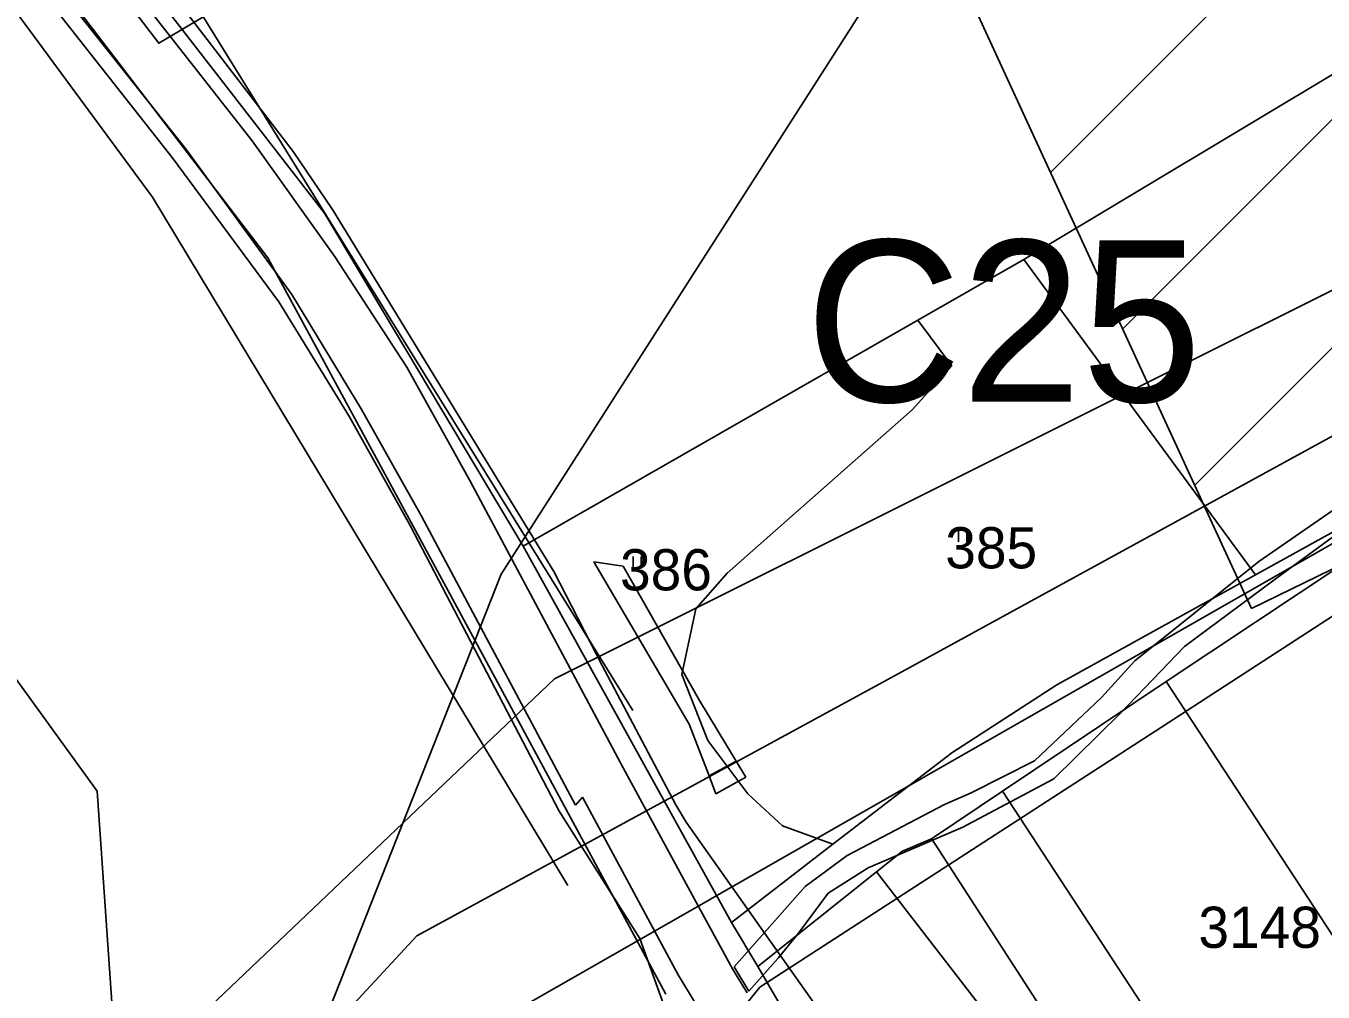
# Model space of a CAD drawing. Extents: x -564810 to -550519, y -1045831 to -1034011.
# Drawn here: x -553559.2 to -553398.7, y -1036730.6 to -1036611.1 of the extents above; entities that cross this region are included whole.
import ezdxf

# ---------------------------------------------------------------- set-up
doc = ezdxf.new("R2010")
doc.units = 0
for name, color, linetype in [('Interakční prvky', 7, 'Continuous'), ('KN stav', 7, 'Continuous'), ('Obvod KPU', 7, 'Continuous'), ('Odvodněné plochy', 7, 'Continuous'), ('označ pol cest', 7, 'Continuous'), ('Parcelní čísla', 7, 'Continuous'), ('Plynovod', 7, 'Continuous'), ('Polní cesty stavající', 7, 'Continuous'), ('přeložka st silnice', 7, 'Continuous'), ('Vedení VN', 7, 'Continuous'), ('Vrstva 16', 7, 'Continuous'), ('Vrstva 39', 7, 'Continuous'), ('Vrstva 4', 7, 'Continuous'), ('zamokř ploch', 7, 'Continuous')]:
    doc.layers.add(name, color=color, linetype=linetype)

msp = doc.modelspace()

# ---------------------------------------------------------------- linework, layer by layer
at = {"layer": 'Interakční prvky'}
for points in [[(-553633.54, -1036491.59), (-553540.33, -1036604.94), (-553484.09, -1036695.78)], [(-553640.77, -1036512.49), (-553602.2, -1036552.69), (-553543.55, -1036632.27), (-553492.12, -1036717.48)]]:
    msp.add_lwpolyline(points, dxfattribs=at)
at = {"layer": 'KN stav'}
for p, q in [((-553558.07, -1036587.98), (-553522.25, -1036634.24)), ((-553529.26, -1036639.79), (-553558.94, -1036600.95)), ((-553435.71, -1036639.99), (-553370.26, -1036600.76)), ((-553522.25, -1036634.24), (-553497.66, -1036675.47)), ((-553506.43, -1036681.97), (-553529.26, -1036639.79)), ((-553448.81, -1036647.49), (-553435.71, -1036639.99)), ((-553435.71, -1036639.99), (-553407.02, -1036679.01)), ((-553497.66, -1036675.47), (-553448.81, -1036647.49)), ((-553448.81, -1036647.49), (-553444.6, -1036653.12)), ((-553444.6, -1036653.12), (-553449.53, -1036658.59)), ((-553449.53, -1036658.59), (-553472.43, -1036678.8)), ((-553407.02, -1036679.01), (-553394.46, -1036672.05)), ((-553497.66, -1036675.47), (-553471.9, -1036722.05)), ((-553396.09, -1036677.6), (-553418.09, -1036692.22)), ((-553472.43, -1036678.8), (-553476.28, -1036683.2)), ((-553407.02, -1036679.01), (-553431.61, -1036692.64)), ((-553480, -1036730.9), (-553506.43, -1036681.97)), ((-553476.28, -1036683.2), (-553478.03, -1036691.34)), ((-553478.03, -1036691.34), (-553474.8, -1036699.52)), ((-553418.09, -1036692.22), (-553438.33, -1036705.77)), ((-553418.09, -1036692.22), (-553390.79, -1036733.87)), ((-553431.61, -1036692.64), (-553444.62, -1036701.02)), ((-553474.8, -1036699.52), (-553469.87, -1036706.13)), ((-553444.62, -1036701.02), (-553459.32, -1036712.35)), ((-553469.87, -1036706.13), (-553465.55, -1036710.06)), ((-553438.33, -1036705.77), (-553447.13, -1036711.67)), ((-553465.55, -1036710.06), (-553459.32, -1036712.35)), ((-553447.13, -1036711.67), (-553450.7, -1036713.2)), ((-553459.32, -1036712.35), (-553471.9, -1036722.05)), ((-553450.7, -1036713.2), (-553453.94, -1036715.78)), ((-553453.94, -1036715.78), (-553468.61, -1036727.47)), ((-553453.94, -1036715.78), (-553423.34, -1036755.23)), ((-553471.9, -1036722.05), (-553468.61, -1036727.47)), ((-553468.61, -1036727.47), (-553462.54, -1036737.9))]:
    msp.add_line(p, q, dxfattribs=at)
at = {"layer": 'Obvod KPU'}
for p, q in [((-553418.65, -1036697.87), (-553343.59, -1036649.12)), ((-553468.39, -1036730.06), (-553418.65, -1036697.87)), ((-553475.47, -1036738.86), (-553468.39, -1036730.06))]:
    msp.add_line(p, q, dxfattribs=at)
at = {"layer": 'Odvodněné plochy'}
for points in [[(-553633.04, -1036487.54), (-553597.98, -1036541.23), (-553542.77, -1036613.21), (-553461.8, -1036565.34), (-553407.51, -1036683.16)], [(-553407.51, -1036683.16), (-553396.09, -1036677.6), (-553372.87, -1036658.98), (-553350.16, -1036646.75), (-553344.21, -1036650.11), (-553341.29, -1036643.5), (-553288.08, -1036612.47), (-553282.13, -1036612.36), (-553278.1, -1036608.45), (-553250.22, -1036595.48), (-553251.31, -1036592.77), (-553247.19, -1036591.04), (-553247.19, -1036591.04), (-553246.36, -1036593.65), (-553217.85, -1036581.51), (-553188.2, -1036567.5), (-553156.51, -1036550.95), (-553100.66, -1036531.24)]]:
    msp.add_lwpolyline(points, dxfattribs=at)
at = {"layer": 'Plynovod'}
msp.add_lwpolyline([(-554428.56, -1035578.55), (-554428.56, -1035578.55), (-554428.56, -1035578.55), (-554027.79, -1036081.22), (-553723.76, -1036467.01), (-553550.38, -1036705.78), (-553550.38, -1036705.78), (-553522.74, -1037110.43), (-553438.57, -1037242.38), (-553213.69, -1037591.73), (-553193.58, -1037703.57), (-553145.84, -1037777.72), (-553110.67, -1037838.04), (-552972.47, -1038070.52), (-552972.47, -1038070.52), (-552302.85, -1038878.56)], dxfattribs=at)
at = {"layer": 'Polní cesty stavající'}
for p, q in [((-553404.76, -1036679.68), (-553389.85, -1036668.71)), ((-553397.55, -1036671.1), (-553406.62, -1036677.35)), ((-553485.28, -1036677.92), (-553488.93, -1036677.4)), ((-553488.93, -1036677.4), (-553477.1, -1036697.48)), ((-553475.85, -1036694.56), (-553485.28, -1036677.92)), ((-553406.62, -1036677.35), (-553421.94, -1036689.65)), ((-553415.81, -1036687.87), (-553404.76, -1036679.68)), ((-553423.73, -1036696.11), (-553415.81, -1036687.87)), ((-553421.94, -1036689.65), (-553426.08, -1036694.2)), ((-553471.3, -1036702.07), (-553475.85, -1036694.56)), ((-553426.08, -1036694.2), (-553434.38, -1036702.01)), ((-553431.98, -1036704.26), (-553423.73, -1036696.11)), ((-553477.1, -1036697.48), (-553474.66, -1036703.89)), ((-553474.66, -1036703.89), (-553471.3, -1036702.07)), ((-553471.3, -1036702.07), (-553474.66, -1036703.89)), ((-553470.09, -1036704.07), (-553471.3, -1036702.07)), ((-553434.38, -1036702.01), (-553442.23, -1036706.01)), ((-553474.66, -1036703.89), (-553473.81, -1036706.11)), ((-553473.81, -1036706.11), (-553470.09, -1036704.07)), ((-553443.25, -1036710.26), (-553431.98, -1036704.26)), ((-553442.23, -1036706.01), (-553445.53, -1036707.43)), ((-553445.53, -1036707.43), (-553457.57, -1036713.76)), ((-553454.97, -1036715.27), (-553443.25, -1036710.26)), ((-553457.57, -1036713.76), (-553462.77, -1036717.57)), ((-553459.9, -1036718.42), (-553454.97, -1036715.27)), ((-553462.77, -1036717.57), (-553471.54, -1036727.51)), ((-553463.58, -1036723.36), (-553459.9, -1036718.42)), ((-553466.12, -1036726.47), (-553463.58, -1036723.36)), ((-553471.54, -1036727.51), (-553469.75, -1036730.54)), ((-553469.75, -1036730.54), (-553466.12, -1036726.47))]:
    msp.add_line(p, q, dxfattribs=at)
at = {"layer": 'přeložka st silnice'}
for p, q in [((-553432.38, -1036629.19), (-552401.91, -1035598.72)), ((-553423.45, -1036648.55), (-552432.49, -1035657.58)), ((-553414.53, -1036667.91), (-552427.47, -1035680.85))]:
    msp.add_line(p, q, dxfattribs=at)
at = {"layer": 'Vedení VN'}
for points in [[(-553567.53, -1034875.85), (-552617.75, -1036041.77), (-552525.91, -1036160.49), (-552512.48, -1036183.11), (-552698.29, -1036379.56), (-552912.35, -1036500.4), (-553117.93, -1036544.92), (-553344, -1036644.56), (-553507.2, -1036737.84), (-553648.49, -1036896.84), (-553694.41, -1037244.51), (-553658.38, -1037334.97)], [(-553684.52, -1037352.63), (-553725.5, -1037238.15), (-553666.15, -1036855.85), (-553493.77, -1036691.9), (-553319.98, -1036604.98), (-553120.76, -1036515.94), (-552942.02, -1036478.49), (-552709.59, -1036345.64), (-552689.1, -1036325.85), (-552549.22, -1036164.73)], [(-553294.31, -1036605.55), (-553373.57, -1036648.74), (-553451.25, -1036691.25), (-553510.82, -1036723.68), (-553562.2, -1036779.16), (-553608.71, -1036829.76), (-553656.52, -1036881.98), (-553666.45, -1036950.74), (-553677.06, -1037025.03), (-553686.97, -1037093.28), (-553698.77, -1037175.72), (-553707.94, -1037241.65), (-553688.47, -1037297.17), (-553671.53, -1037343.76)]]:
    msp.add_lwpolyline(points, dxfattribs=at)
at = {"layer": 'Vrstva 16'}
msp.add_lwpolyline([(-553156.59, -1036068.23), (-553271.19, -1036329.95), (-553326.01, -1036402.23), (-553438.12, -1036581.7), (-553500.41, -1036678.91), (-553537.78, -1036773.63), (-553654.88, -1036898.25), (-553794.4, -1036983), (-553946.38, -1037072.73), (-554030.85, -1037138.79), (-554140.47, -1037236), (-554172.86, -1037275.88), (-554409.55, -1037435.4), (-554469.35, -1037482.76), (-554516.68, -1037530.12), (-554559.04, -1037579.97), (-554569, -1037664.72), (-554661.19, -1037749.47), (-554907.84, -1037851.66), (-555066.31, -1037953.36)], dxfattribs=at)
at = {"layer": 'Vrstva 39'}
for p, q in [((-553572.91, -1036572.12), (-553531.21, -1036625.29)), ((-553539.33, -1036626.41), (-553578.81, -1036576.53)), ((-553526.31, -1036644.29), (-553539.33, -1036626.41)), ((-553531.21, -1036625.29), (-553521.02, -1036639.56)), ((-553521.02, -1036639.56), (-553512.05, -1036653.32)), ((-553517.71, -1036658.47), (-553526.31, -1036644.29)), ((-553512.05, -1036653.32), (-553504.27, -1036667.32)), ((-553510.26, -1036671.76), (-553517.71, -1036658.47)), ((-553504.27, -1036667.32), (-553485.27, -1036702.89)), ((-553491.19, -1036707.53), (-553510.26, -1036671.76)), ((-553485.27, -1036702.89), (-553476.47, -1036719.16)), ((-553490.34, -1036706.54), (-553491.19, -1036707.53)), ((-553478.49, -1036728.5), (-553490.34, -1036706.54)), ((-553476.47, -1036719.16), (-553471.76, -1036727.76)), ((-553471.76, -1036727.76), (-553469.95, -1036730.76)), ((-553471.64, -1036739.69), (-553478.49, -1036728.5))]:
    msp.add_line(p, q, dxfattribs=at)
for points in [[(-553467.64, -1036745.47), (-553470.22, -1036748.21), (-553474.48, -1036742.54), (-553476.12, -1036737.78), (-553480.13, -1036732.61), (-553483.22, -1036724.01), (-553493.2, -1036708.26), (-553511.64, -1036672.9), (-553519.18, -1036659.44), (-553527.92, -1036645.21), (-553541.11, -1036627.36), (-553580.33, -1036577.6)], [(-553539.38, -1036609.38), (-553526.14, -1036626.63), (-553521.25, -1036633.8), (-553493.89, -1036678.59), (-553487.9, -1036690.23), (-553478.76, -1036707.48), (-553477.49, -1036709.63), (-553459.52, -1036735.09), (-553463.79, -1036740.64), (-553467.64, -1036745.47)]]:
    msp.add_lwpolyline(points, dxfattribs=at)
at = {"layer": 'Vrstva 4'}
for p, q in [((-553438.33, -1036705.77), (-553409.64, -1036749.59)), ((-553418.66, -1036755.64), (-553447.13, -1036711.66))]:
    msp.add_line(p, q, dxfattribs=at)
at = {"layer": 'zamokř ploch'}
for p, q in [((-553443.77, -1036673.44), (-553443.77, -1036674.94)), ((-553442.77, -1036673.44), (-553442.77, -1036674.94)), ((-553484.07, -1036676.73), (-553484.07, -1036678.23)), ((-553483.07, -1036676.73), (-553483.07, -1036678.23))]:
    msp.add_line(p, q, dxfattribs=at)

# ---------------------------------------------------------------- texts
at = {"layer": 'označ pol cest'}
msp.add_text('C25', height=20, dxfattribs=at).set_placement((-553462.73, -1036657.59))
at = {"layer": 'Parcelní čísla'}
for s, p in [('385', (-553445.42, -1036678.21)), ('386', (-553485.68, -1036680.93)), ('3148', (-553414.09, -1036725.18))]:
    msp.add_text(s, height=5.1, dxfattribs=at).set_placement(p)

doc.saveas('drawing.dxf')
